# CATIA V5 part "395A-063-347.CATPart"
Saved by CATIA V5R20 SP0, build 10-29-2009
Part number: 395A-063-347
Source: Unknown
Property "ARTICLENO": "395A-063-347"
Property "B": "15"
Property "BOMINFO": "395A-063-347"
Property "C": "20.000"
Property "CODE": "395A-063-347"
Property "D": "63.000"
Property "D1": "75.000"
Property "D2": "5x20"
Property "D3": "30"
Property "D5": "48"
Property "D6": "45.000"
Property "H": "7.500"
Property "L": "347.000"
Property "L1": "14.000"
Property "L2": "295.000"
Property "L3": "17.000"
Property "L4": "20"
Property "LINA": "395A-063-347"
Property "M": "24.000"
Property "M1": "18.000"
Property "M2": "20.000"
Property "MAXLOAD": "12500 Kg"
Property "MDW": "25000 Kg"
Property "NB": "395A-063-347"
Property "NBSYN": "$CODE."
Property "NN": "395A"
Property "NT": "Pin"
Property "P": "8"
Property "S": "17.000"
Property "SUPPLIER": "CF"
Bounding box of the stored display mesh (mm): x 0 to 347, y -39 to 37.5, z -37.5 to 37.5
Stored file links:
  C:\Users\Utente\Desktop\3D files 395A\395A-063-347.CATPart
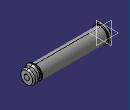
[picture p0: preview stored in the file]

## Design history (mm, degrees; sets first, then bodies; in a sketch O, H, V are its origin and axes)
Body1 "Geometry.1" (main body)
  Solid1 "395A-063-347.catpart": solid without history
